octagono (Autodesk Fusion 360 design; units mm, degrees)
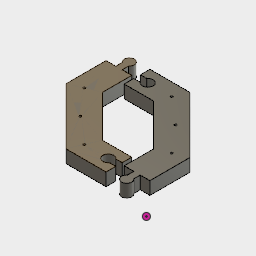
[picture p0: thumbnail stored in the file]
sketch "Sketch1" plane through (0, 0, 0) normal (0, 1, 0) x axis (1, 0, 0)
  line L1 (-62.132, 150) -> (0, 150)
  line L2 (-150, 62.132) -> (-62.132, 150)
  line L3 (-150, 0) -> (-150, 62.132)
  line L4 (-110, 45.5635) -> (-45.5635, 110)
  line L5 (-110, 0) -> (-110, 45.5635)
  line L6 (-45.5635, 110) -> (0, 110)
  line L7 (-135, 0) -> (-150, 0)
  line L8 (-135, 10) -> (-135, 0)
  line L9 (-125, 0) -> (-110, 0)
  line L10 (-125, 10) -> (-125, 0)
  line L11 (0, 125) -> (0, 110)
  line L12 (10, 125) -> (0, 125)
  line L13 (0, 135) -> (0, 150)
  line L14 (10, 135) -> (0, 135)
  arc A1 centre (-130, 16.6667) radius 8.3333 clockwise from (-135, 10) to (-125, 10)
  arc A2 centre (16.1071, 130) radius 7.8929 clockwise from (10, 135) to (10, 125)
  circle C1 centre (-130, 53.8478) radius 1.71
  circle C2 centre (-95, 95) radius 1.71
  circle C3 centre (-53.8478, 130) radius 1.71
  dimension "d3" diameter C1 = 3.42
  dimension "d4" diameter C2 = 3.42
  dimension "d5" diameter C3 = 3.42
extrude "Extrude1" sketch "Sketch1" blind 20
move_face "MoveFace1"
move "Move1"
sketch "Sketch2" plane through (0, 0, 0) normal (0, 1, 0) x axis (1, 0, 0)
move "Move2"
copy_paste_bodies "CopyPasteBodies1"
move "Move3"
move "Move4"
move "Move5"
move "Move6"
sketch "Sketch3" plane through (0, 0, 0) normal (0, 1, 0) x axis (1, 0, 0)
sketch "Sketch4" plane through (0, 0, 0) normal (0, 1, 0) x axis (1, 0, 0)
move "Move7"
sketch "Sketch5" plane through (0, 20, 0) normal (0, 1, 0) x axis (-1, 0, 0)
  line L1 (196.1473, -158.5036) -> (181.1473, -158.5036)
  line L2 (196.1473, -168.5036) -> (196.1473, -158.5036)
  line L3 (206.1473, -158.5036) -> (206.1473, -168.5036)
  line L4 (221.1473, -158.5036) -> (206.1473, -158.5036)
  line L5 (221.1473, -96.3716) -> (221.1473, -158.5036)
  line L6 (133.2794, -8.5036) -> (221.1473, -96.3716)
  line L7 (71.1473, -8.5036) -> (133.2794, -8.5036)
  line L8 (71.1473, -23.5036) -> (71.1473, -8.5036)
  line L9 (81.1473, -23.5036) -> (71.1473, -23.5036)
  line L10 (71.1473, -33.5036) -> (81.1473, -33.5036)
  line L11 (71.1473, -48.5036) -> (71.1473, -33.5036)
  line L12 (116.7108, -48.5036) -> (71.1473, -48.5036)
  line L13 (181.1473, -112.9401) -> (116.7108, -48.5036)
  line L14 (181.1473, -158.5036) -> (181.1473, -112.9401)
  circle C1 centre (166.1473, -63.5036) radius 1.71
  circle C2 centre (201.1473, -104.6559) radius 1.71
  circle C3 centre (124.9951, -28.5036) radius 1.71
  arc A1 centre (201.1473, -174.6108) radius 7.8929 clockwise from (206.1473, -168.5036) to (196.1473, -168.5036)
  arc A2 centre (87.814, -28.5036) radius 8.3333 clockwise from (81.1473, -23.5036) to (81.1473, -33.5036)
  dimension "d10" radius A1 = 7.8929
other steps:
base_feature "Base Feature"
